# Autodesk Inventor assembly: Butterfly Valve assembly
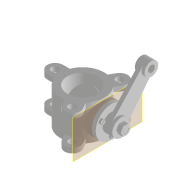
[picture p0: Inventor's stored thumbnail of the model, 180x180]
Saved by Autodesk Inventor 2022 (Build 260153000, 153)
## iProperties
Created: 2019-03
Part Number: Butterfly Valve assembly
Document SubType Name: Assembly
Designer: LENOVO-CADCIM
Author: LENOVO-CADCIM
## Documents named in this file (10)
- D:\PROJECTS_2021\Resources\Tutorial Files\c09_Inv_2022_tut\c09_Inv_2021_tut\c09_Inv_tut_2021\c09_tut01_inv\Butterfly Valve\Butterfly Valve assembly.iam
- D:\PROJECTS_2021\Resources\Tutorial Files\c09_Inv_2022_tut\c09_Inv_2021_tut\c09_Inv_tut_2021\c09_tut01_inv\Butterfly Valve\Body.ipt
- D:\PROJECTS_2021\Resources\Tutorial Files\c09_Inv_2022_tut\c09_Inv_2021_tut\c09_Inv_tut_2021\c09_tut01_inv\Butterfly Valve\Shaft.ipt
- D:\PROJECTS_2021\Resources\Tutorial Files\c09_Inv_2022_tut\c09_Inv_2021_tut\c09_Inv_tut_2021\c09_tut01_inv\Butterfly Valve\Retainer.ipt
- D:\PROJECTS_2021\Resources\Tutorial Files\c09_Inv_2022_tut\c09_Inv_2021_tut\c09_Inv_tut_2021\c09_tut01_inv\Butterfly Valve\Arm.ipt
- D:\PROJECTS_2021\Resources\Tutorial Files\c09_Inv_2022_tut\c09_Inv_2021_tut\c09_Inv_tut_2021\c09_tut01_inv\Butterfly Valve\Plate.ipt
- D:\PROJECTS_2021\Resources\Tutorial Files\c09_Inv_2022_tut\c09_Inv_2021_tut\c09_Inv_tut_2021\c09_tut01_inv\Butterfly Valve\scew1.ipt
- D:\PROJECTS_2021\Resources\Tutorial Files\c09_Inv_2022_tut\c09_Inv_2021_tut\c09_Inv_tut_2021\c09_tut01_inv\Butterfly Valve\Screw.ipt
- D:\PROJECTS_2021\Resources\Tutorial Files\c09_Inv_2022_tut\c09_Inv_2021_tut\c09_Inv_tut_2021\c09_tut01_inv\Butterfly Valve\Parallel key.ipt
- D:\PROJECTS_2021\Resources\Tutorial Files\c09_Inv_2022_tut\c09_Inv_2021_tut\c09_Inv_tut_2021\c09_tut01_inv\Butterfly Valve\Nut.ipt
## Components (12 placed, 9 different names)
1. Body:1 — Insert:1, Insert:2, Mate:1, Angle:2, Angle:3
2. Shaft:1 — Insert:1, Angle:1, Angle:2, Mate:2, Insert:9, Insert:10, Insert:11
3. Retainer:1 — Insert:2, Mate:1, Insert:3, Insert:6, Insert:7, Insert:8
4. Arm:1 — Insert:3, Angle:1, Mate:3, Mate:4
5. Screw:1 — Insert:6
6. Screw:2 — Insert:7
7. Screw:3 — Insert:8
8. Parallel key:1 — Mate:2, Mate:3, Mate:4
9. Nut:1 — Insert:9, Angle:3
10. Plate:1 — Insert:10, Insert:11, Insert:12, Insert:13
11. scew1:1 — Insert:12
12. scew1:2 — Insert:13
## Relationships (18: Insert 11, Mate 4, Angle 3)
- Insert:1: Body:1 ↔ Shaft:1
- Insert:2: Body:1 ↔ Retainer:1
- Mate:1: Body:1 ↔ Retainer:1
- Insert:3: Retainer:1 ↔ Arm:1
- Angle:1: Shaft:1 ↔ Arm:1
- Angle:2: Body:1 ↔ Shaft:1
- Insert:6: Retainer:1 ↔ Screw:1
- Insert:7: Retainer:1 ↔ Screw:2
- Insert:8: Retainer:1 ↔ Screw:3
- Mate:2: Shaft:1 ↔ Parallel key:1
- Mate:3: Arm:1 ↔ Parallel key:1
- Mate:4: Arm:1 ↔ Parallel key:1
- Insert:9: Shaft:1 ↔ Nut:1
- Angle:3: Body:1 ↔ Nut:1
- Insert:10: Shaft:1 ↔ Plate:1
- Insert:11: Shaft:1 ↔ Plate:1
- Insert:12: Plate:1 ↔ scew1:1
- Insert:13: Plate:1 ↔ scew1:2
